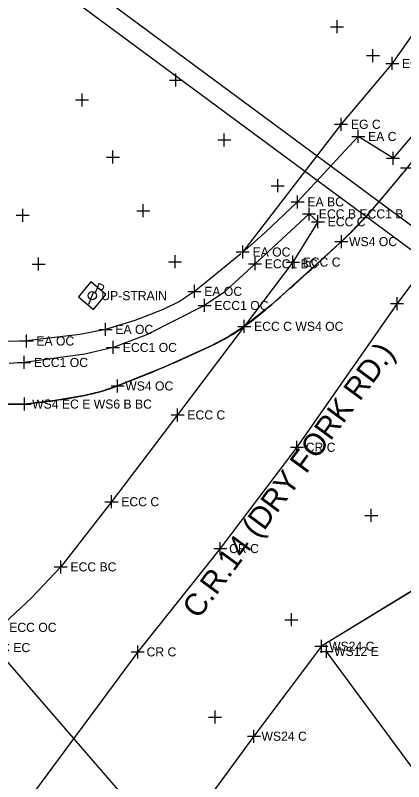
# Model space of a CAD drawing. Extents: x 1324236 to 1326110, y 459090 to 460782.
# Drawn here: x 1325315.8 to 1325375.5, y 460303.9 to 460421.8 of the extents above; entities that cross this region are included whole.
import ezdxf

# ---------------------------------------------------------------- set-up
doc = ezdxf.new("R2010")
doc.units = 0
for name, color, linetype in [('BD_X_Canopy', 7, 'Continuous'), ('DR_X_Ditch', 7, 'Continuous'), ('DR_X_Storm_Sewer', 7, 'Continuous'), ('DT_X_Island', 7, 'Continuous'), ('DT_X_Void', 7, 'Continuous'), ('DV_X_Property_Line', 7, 'Continuous'), ('E-RW-ODOT', 7, 'Continuous'), ('LT_X_Poles', 7, 'Continuous'), ('PM_X_CL_Double_Solid', 7, 'Continuous'), ('PM_X_Edge_Line', 7, 'Continuous'), ('PM_X_Stop_Line', 7, 'Continuous'), ('PV_X_Shoulder', 7, 'Continuous'), ('RD_X_Concrete_Barrier', 7, 'Continuous'), ('RW_X_CL', 7, 'Continuous'), ('SG_X_Foundation', 7, 'Continuous'), ('SH_Data', 7, 'Continuous'), ('VG_X_Flower_Bed', 7, 'Continuous')]:
    doc.layers.add(name, color=color, linetype=linetype)

msp = doc.modelspace()

# ---------------------------------------------------------------- linework, layer by layer
at = {"layer": 'BD_X_Canopy'}
msp.add_lwpolyline([(1325487.31, 460531.49), (1325482.01, 460524.62), (1325468.2, 460505.38), (1325449.72, 460480.14), (1325435.41, 460460.81), (1325430.06, 460453.47), (1325411.08, 460426.97), (1325392.29, 460401.31), (1325374.47, 460377.45), (1325359.08, 460355.34), (1325347.31, 460339.76), (1325334.63, 460323.86), (1325318.91, 460302.58), (1325303.42, 460281.57), (1325299.27, 460276.07), (1325289.28, 460262.48), (1325282.05, 460252.54), (1325264.96, 460229.27), (1325246.47, 460204.3), (1325228.59, 460180.03), (1325210.75, 460156.01)], dxfattribs=at)
at = {"layer": 'DR_X_Ditch'}
for points in [[(1325402.39, 460435.17), (1325382.22, 460409.68), (1325373.86, 460399.82), (1325368.52, 460403.17), (1325359.2, 460393.1), (1325354.22, 460388.4), (1325351.12, 460385.69)], [(1325392.09, 460419.54), (1325383.77, 460408.68), (1325376.02, 460398.36), (1325369.87, 460391.03), (1325369.87, 460391.03), (1325365.93, 460386.99), (1325365.93, 460386.99), (1325355.22, 460377.31), (1325355.22, 460377.31), (1325351, 460373.95), (1325351, 460373.95), (1325348.53, 460372.33), (1325345.92, 460370.94), (1325345.92, 460370.94), (1325338.78, 460367.73), (1325331.53, 460364.78), (1325331.53, 460364.78), (1325329.02, 460363.94), (1325326.46, 460363.32), (1325326.46, 460363.32), (1325321.86, 460362.54), (1325317.23, 460361.99), (1325317.23, 460361.99)], [(1325317.23, 460361.99), (1325307.45, 460362.12), (1325307.45, 460362.12), (1325302.92, 460362.62), (1325302.92, 460362.62), (1325294.72, 460364.16), (1325294.72, 460364.16), (1325283.25, 460366.46), (1325283.25, 460366.46), (1325276.4, 460368.15), (1325276.4, 460368.15), (1325264.53, 460371.79), (1325264.53, 460371.79), (1325232.42, 460381.61), (1325201.72, 460390.92), (1325171.39, 460399.9)]]:
    msp.add_lwpolyline(points, dxfattribs=at)
at = {"layer": 'DR_X_Storm_Sewer'}
for p, q in [((1325379.64, 460334.98), (1325362.86, 460324.73)), ((1325362.86, 460324.73), (1325352.48, 460310.88)), ((1325376.81, 460306.09), (1325363.64, 460323.93)), ((1325352.48, 460310.88), (1325339.85, 460293.66))]:
    msp.add_line(p, q, dxfattribs=at)
at = {"layer": 'DT_X_Island'}
for p, q in [((1325392.29, 460401.31), (1325374.47, 460377.45)), ((1325374.47, 460377.45), (1325359.08, 460355.34)), ((1325359.08, 460355.34), (1325347.31, 460339.76)), ((1325347.31, 460339.76), (1325334.63, 460323.86)), ((1325334.63, 460323.86), (1325318.91, 460302.58))]:
    msp.add_line(p, q, dxfattribs=at)
at = {"layer": 'DV_X_Property_Line'}
for p, q in [((1325373.73, 460413.41), (1325373.73, 460415.41)), ((1325372.73, 460414.41), (1325374.73, 460414.41)), ((1325365.88, 460404.04), (1325365.88, 460406.04)), ((1325364.88, 460405.04), (1325366.88, 460405.04)), ((1325367.52, 460403.17), (1325369.52, 460403.17)), ((1325368.52, 460402.17), (1325368.52, 460404.17)), ((1325373.86, 460398.82), (1325373.86, 460400.82)), ((1325372.86, 460399.82), (1325374.86, 460399.82)), ((1325359.2, 460392.1), (1325359.2, 460394.1)), ((1325358.2, 460393.1), (1325360.2, 460393.1)), ((1325360.95, 460390.25), (1325360.95, 460392.25)), ((1325359.95, 460391.25), (1325361.95, 460391.25)), ((1325362.31, 460389.04), (1325362.31, 460391.04)), ((1325361.31, 460390.04), (1325363.31, 460390.04)), ((1325349.77, 460385.39), (1325351.77, 460385.39)), ((1325350.77, 460384.39), (1325350.77, 460386.39)), ((1325352.65, 460382.57), (1325352.65, 460384.57)), ((1325358.47, 460382.84), (1325358.47, 460384.84)), ((1325351.65, 460383.57), (1325353.65, 460383.57)), ((1325357.47, 460383.84), (1325359.47, 460383.84)), ((1325343.34, 460378.33), (1325343.34, 460380.33)), ((1325342.34, 460379.33), (1325344.34, 460379.33)), ((1325343.9, 460377.16), (1325345.9, 460377.16)), ((1325344.9, 460376.16), (1325344.9, 460378.16)), ((1325351, 460372.95), (1325351, 460374.95)), ((1325329.68, 460372.48), (1325329.68, 460374.48)), ((1325350, 460373.95), (1325352, 460373.95)), ((1325317.54, 460370.7), (1325317.54, 460372.7)), ((1325328.68, 460373.48), (1325330.68, 460373.48)), ((1325316.54, 460371.7), (1325318.54, 460371.7)), ((1325330.83, 460369.7), (1325330.83, 460371.7)), ((1325329.83, 460370.7), (1325331.83, 460370.7)), ((1325317.16, 460367.39), (1325317.16, 460369.39)), ((1325316.16, 460368.39), (1325318.16, 460368.39)), ((1325340.75, 460359.32), (1325340.75, 460361.32)), ((1325339.75, 460360.32), (1325341.75, 460360.32)), ((1325330.59, 460345.96), (1325330.59, 460347.96)), ((1325329.59, 460346.96), (1325331.59, 460346.96)), ((1325322.78, 460335.94), (1325322.78, 460337.94)), ((1325321.78, 460336.94), (1325323.78, 460336.94))]:
    msp.add_line(p, q, dxfattribs=at)
at = {"layer": 'E-RW-ODOT'}
msp.add_line((1325254.99, 460391.14), (1325401.65, 460221.67), dxfattribs=at)
at = {"layer": 'LT_X_Poles'}
for points in [[(1325435.41, 460460.81), (1325430.06, 460453.47), (1325411.08, 460426.97), (1325392.29, 460401.31), (1325374.47, 460377.45)], [(1325392.09, 460419.54), (1325383.77, 460408.68), (1325376.02, 460398.36), (1325369.87, 460391.03), (1325369.87, 460391.03), (1325365.93, 460386.99), (1325365.93, 460386.99), (1325355.22, 460377.31), (1325355.22, 460377.31), (1325351, 460373.95), (1325351, 460373.95), (1325348.53, 460372.33), (1325345.92, 460370.94), (1325345.92, 460370.94), (1325338.78, 460367.73), (1325331.53, 460364.78), (1325331.53, 460364.78), (1325329.02, 460363.94), (1325326.46, 460363.32), (1325326.46, 460363.32), (1325321.86, 460362.54), (1325317.23, 460361.99), (1325317.23, 460361.99)], [(1325552.53, 460052.37), (1325537.68, 460074.22), (1325518.91, 460101.44), (1325501.6, 460127.06), (1325483.41, 460153.55), (1325465.49, 460179.7), (1325447.45, 460205.76), (1325428.78, 460232.55), (1325409.11, 460260.88), (1325391.07, 460286.18), (1325376.81, 460306.09), (1325363.64, 460323.93)]]:
    msp.add_lwpolyline(points, dxfattribs=at)
at = {"layer": 'PM_X_CL_Double_Solid'}
msp.add_line((1325392.29, 460401.31), (1325374.47, 460377.45), dxfattribs=at)
at = {"layer": 'PM_X_Edge_Line'}
for centre, radius, start, end in [((1325239.64, 460506.66), 174.16, 318.3958, 321.5449), ((1325324.68, 460431.16), 60.44, 313.0487, 318.3958), ((1325070.42, 460703.35), 432.9, 311.1375, 313.0487), ((1325315.49, 460422.8), 60.39, 306.019, 311.1375), ((1325332.57, 460399.3), 31.35, 295.2128, 306.019), ((1325252.03, 460570.35), 220.41, 291.1428, 295.2128), ((1325320.7, 460392.79), 30.03, 281.0548, 291.1428), ((1325308.51, 460455.18), 93.6, 275.3453, 281.0548), ((1325314.47, 460520.12), 158.15, 267.4556, 270.9983)]:
    msp.add_arc(centre, radius, start, end, dxfattribs=at)
at = {"layer": 'PM_X_Stop_Line'}
msp.add_lwpolyline([(1325379.64, 460334.98), (1325362.86, 460324.73), (1325352.48, 460310.88), (1325339.85, 460293.66)], dxfattribs=at)
at = {"layer": 'PV_X_Shoulder'}
for points in [[(1325402.99, 460452.07), (1325393.04, 460442.09), (1325373.73, 460414.41), (1325365.88, 460405.04), (1325350.77, 460385.39)], [(1325350.45, 460385.12), (1325345.12, 460380.73), (1325343.34, 460379.33), (1325341.02, 460377.79), (1325338.54, 460376.54), (1325334.16, 460374.85), (1325329.68, 460373.48), (1325325.72, 460372.67), (1325317.54, 460371.7), (1325315.28, 460371.62), (1325313.02, 460371.78), (1325309.42, 460372.34), (1325305.86, 460373.15), (1325286.15, 460376.13), (1325266.52, 460379.99), (1325235.1, 460388.97), (1325203.91, 460398.61), (1325173.61, 460407.67)], [(1325360.95, 460391.25), (1325362.31, 460390.04), (1325358.47, 460383.84), (1325351, 460373.95), (1325340.75, 460360.32), (1325330.59, 460346.96), (1325322.78, 460336.94), (1325318.25, 460332.11), (1325313.37, 460327.63)], [(1325360.95, 460391.25), (1325352.65, 460383.57), (1325347.86, 460379.18), (1325347.86, 460379.18), (1325344.9, 460377.16), (1325344.9, 460377.16), (1325335.88, 460372.61), (1325335.88, 460372.61), (1325330.83, 460370.7), (1325330.83, 460370.7), (1325326.48, 460369.68), (1325326.48, 460369.68), (1325317.16, 460368.39), (1325317.16, 460368.39), (1325314.85, 460368.25)]]:
    msp.add_lwpolyline(points, dxfattribs=at)
at = {"layer": 'RD_X_Concrete_Barrier'}
msp.add_line((1325327.09, 460377.38), (1325327.9, 460379.32), dxfattribs=at)
msp.add_circle((1325327.63, 460378.67), 0.63, dxfattribs=at)
at = {"layer": 'RW_X_CL'}
for p, q in [((1325365.26, 460419.05), (1325365.26, 460421.05)), ((1325364.26, 460420.05), (1325366.26, 460420.05)), ((1325370.78, 460414.61), (1325370.78, 460416.61)), ((1325369.78, 460415.61), (1325371.78, 460415.61)), ((1325340.48, 460410.84), (1325340.48, 460412.84)), ((1325339.48, 460411.84), (1325341.48, 460411.84)), ((1325326.07, 460407.79), (1325326.07, 460409.79)), ((1325325.07, 460408.79), (1325327.07, 460408.79)), ((1325347.91, 460401.64), (1325347.91, 460403.64)), ((1325346.91, 460402.64), (1325348.91, 460402.64)), ((1325330.8, 460398.99), (1325330.8, 460400.99)), ((1325329.8, 460399.99), (1325331.8, 460399.99)), ((1325375.02, 460398.36), (1325377.02, 460398.36)), ((1325356.15, 460394.59), (1325356.15, 460396.59)), ((1325355.15, 460395.59), (1325357.15, 460395.59)), ((1325335.48, 460390.74), (1325335.48, 460392.74)), ((1325316.94, 460390.04), (1325316.94, 460392.04)), ((1325334.48, 460391.74), (1325336.48, 460391.74)), ((1325315.94, 460391.04), (1325317.94, 460391.04)), ((1325365.93, 460385.99), (1325365.93, 460387.99)), ((1325364.93, 460386.99), (1325366.93, 460386.99)), ((1325319.39, 460382.53), (1325319.39, 460384.53)), ((1325340.37, 460382.9), (1325340.37, 460384.9)), ((1325318.39, 460383.53), (1325320.39, 460383.53)), ((1325339.37, 460383.9), (1325341.37, 460383.9)), ((1325374.47, 460376.45), (1325374.47, 460378.45)), ((1325373.47, 460377.45), (1325375.47, 460377.45)), ((1325331.53, 460363.78), (1325331.53, 460365.78)), ((1325330.53, 460364.78), (1325332.53, 460364.78)), ((1325317.23, 460360.99), (1325317.23, 460362.99)), ((1325316.23, 460361.99), (1325318.23, 460361.99)), ((1325359.08, 460354.34), (1325359.08, 460356.34)), ((1325358.08, 460355.34), (1325360.08, 460355.34)), ((1325370.52, 460343.86), (1325370.52, 460345.86)), ((1325369.52, 460344.86), (1325371.52, 460344.86)), ((1325347.31, 460338.76), (1325347.31, 460340.76)), ((1325346.31, 460339.76), (1325348.31, 460339.76)), ((1325357.23, 460328.81), (1325359.23, 460328.81)), ((1325358.23, 460327.81), (1325358.23, 460329.81)), ((1325362.86, 460323.73), (1325362.86, 460325.73)), ((1325334.63, 460322.86), (1325334.63, 460324.86)), ((1325361.86, 460324.73), (1325363.86, 460324.73)), ((1325363.64, 460322.93), (1325363.64, 460324.93)), ((1325333.63, 460323.86), (1325335.63, 460323.86)), ((1325362.64, 460323.93), (1325364.64, 460323.93)), ((1325346.51, 460312.83), (1325346.51, 460314.83)), ((1325345.51, 460313.83), (1325347.51, 460313.83)), ((1325352.48, 460309.88), (1325352.48, 460311.88)), ((1325351.48, 460310.88), (1325353.48, 460310.88))]:
    msp.add_line(p, q, dxfattribs=at)
at = {"layer": 'SG_X_Foundation'}
for p, q in [((1325327.43, 460380.79), (1325325.52, 460378.48)), ((1325329.74, 460378.87), (1325327.43, 460380.79)), ((1325325.52, 460378.48), (1325327.83, 460376.56)), ((1325327.83, 460376.56), (1325329.74, 460378.87))]:
    msp.add_line(p, q, dxfattribs=at)
msp.add_lwpolyline([(1325325.52, 460378.48), (1325327.83, 460376.56), (1325329.74, 460378.87), (1325327.43, 460380.79)], close=True, dxfattribs=at)
at = {"layer": 'VG_X_Flower_Bed'}
for p, q in [((1325304.91, 460442.59), (1325427.5, 460351.85)), ((1325303.12, 460440.18), (1325425.72, 460349.44))]:
    msp.add_line(p, q, dxfattribs=at)

# ---------------------------------------------------------------- texts
at = {"layer": 'DT_X_Void'}
msp.add_text('UP-STRAIN', height=1.4, dxfattribs=at).set_placement((1325329.02, 460377.97))
at = {"layer": 'DV_X_Property_Line'}
for s, p in [('EG C', (1325375.23, 460413.71)), ('EG C', (1325367.38, 460404.34)), ('EA C', (1325370.02, 460402.47)), ('EA BC', (1325360.7, 460392.4)), ('ECC B ECC1 B', (1325362.45, 460390.55)), ('ECC C', (1325363.81, 460389.34)), ('EA OC', (1325352.27, 460384.69)), ('ECC1 BC', (1325354.15, 460382.87)), ('ECC C', (1325359.97, 460383.14)), ('EA OC', (1325344.84, 460378.63)), ('ECC1 OC', (1325346.4, 460376.46)), ('EA OC', (1325331.18, 460372.78)), ('ECC C WS4 OC', (1325352.5, 460373.25)), ('EA OC', (1325319.04, 460371)), ('ECC1 OC', (1325332.33, 460370)), ('ECC1 OC', (1325318.66, 460367.69)), ('ECC C', (1325342.25, 460359.62)), ('ECC C', (1325332.09, 460346.26)), ('ECC BC', (1325324.28, 460336.24)), ('ECC OC', (1325314.87, 460326.93)), ('ECC EC', (1325311.03, 460323.82))]:
    msp.add_text(s, height=1.4, dxfattribs=at).set_placement(p)
at = {"layer": 'RD_X_Concrete_Barrier'}
msp.add_text('P', height=1.5, rotation=337.5827, dxfattribs=at).set_placement((1325327.9, 460379.32))
at = {"layer": 'RW_X_CL'}
for s, p in [('WS4 OC', (1325367.1, 460386.29)), ('WS4 OC', (1325332.7, 460364.08)), ('WS4 EC E WS6 B BC', (1325318.39, 460361.29)), ('CR C', (1325360.44, 460354.64)), ('CR C', (1325348.67, 460339.06)), ('WS24 C', (1325364.03, 460324.03)), ('CR C', (1325335.98, 460323.16)), ('WS12 E', (1325364.8, 460323.23)), ('WS24 C', (1325353.64, 460310.18))]:
    msp.add_text(s, height=1.4, dxfattribs=at).set_placement(p)
at = {"layer": 'SH_Data'}
msp.add_text('C.R.14 (DRY FORK RD.)', height=3.4, rotation=53.5406, dxfattribs=at).set_placement((1325343.96, 460328.78))

doc.saveas('drawing.dxf')
